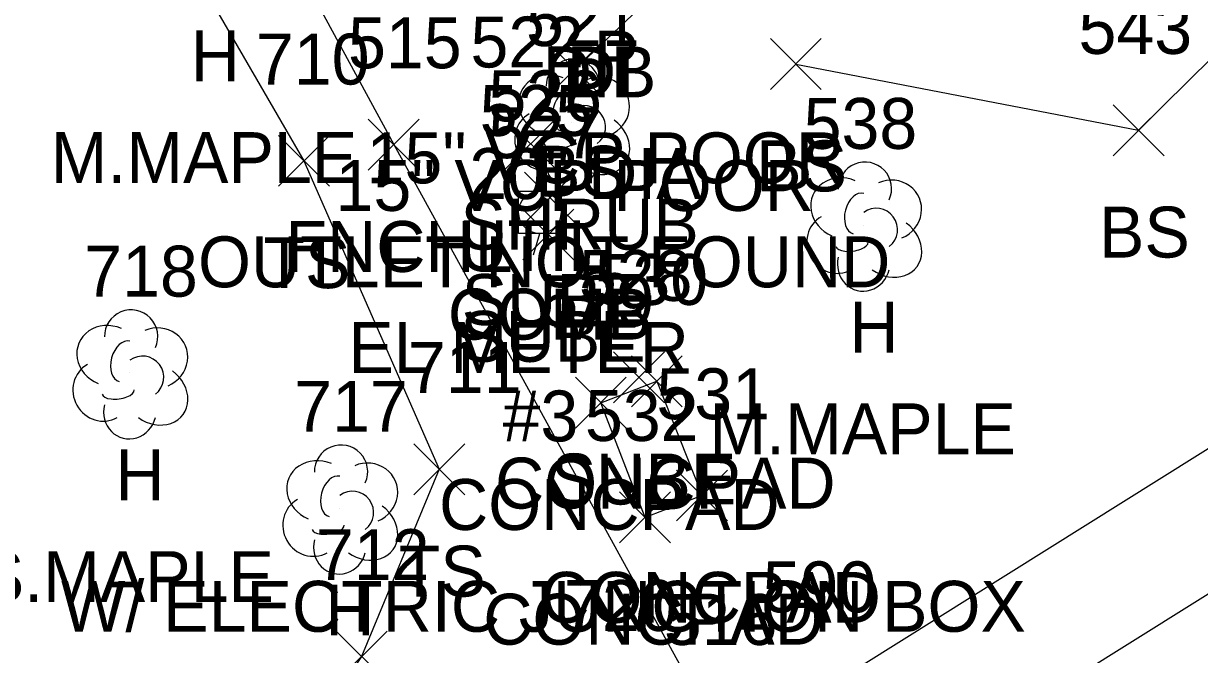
# Model space of a CAD drawing. Extents: x 1462668 to 1465147, y 550359 to 557351.
# Drawn here: x 1464779.74 to 1464825.93, y 552479.73 to 552504.51 of the extents above; entities that cross this region are included whole.
import ezdxf

# ---------------------------------------------------------------- set-up
doc = ezdxf.new("R2010")
doc.units = 0
for name, color, linetype in [('D_A', 7, 'Continuous'), ('D_C', 7, 'Continuous'), ('L_A', 7, 'Continuous'), ('L_C', 7, 'Continuous'), ('L_I', 7, 'Continuous'), ('L_TIC', 7, 'Continuous'), ('LELB', 7, 'Continuous'), ('LFNC', 7, 'Continuous'), ('LS', 7, 'Continuous'), ('LSH', 7, 'Continuous'), ('LTD', 7, 'Continuous'), ('R_I', 7, 'Continuous'), ('RSW', 7, 'Continuous'), ('U_A', 7, 'Continuous'), ('U_C', 7, 'Continuous'), ('U_I', 7, 'Continuous'), ('U_TIC', 7, 'Continuous'), ('UDEFAULT', 7, 'Continuous'), ('UP', 7, 'Continuous')]:
    doc.layers.add(name, color=color, linetype=linetype)

msp = doc.modelspace()

# ---------------------------------------------------------------- linework, layer by layer
at = {"layer": 'L_TIC'}
for points in [[(1464800.392, 552501.712), (1464802.392, 552503.712)], [(1464802.392, 552501.712), (1464800.392, 552503.712)], [(1464809.075, 552501.92), (1464811.075, 552503.92)], [(1464811.075, 552501.92), (1464809.075, 552503.92)], [(1464822.538, 552499.32), (1464824.538, 552501.32)], [(1464824.538, 552499.32), (1464822.538, 552501.32)], [(1464793.283, 552498.755), (1464795.283, 552500.755)], [(1464795.283, 552498.755), (1464793.283, 552500.755)], [(1464789.754, 552498.118), (1464791.754, 552500.118)], [(1464791.754, 552498.118), (1464789.754, 552500.118)], [(1464803.616, 552489.46), (1464805.616, 552491.46)], [(1464805.616, 552489.46), (1464803.616, 552491.46)], [(1464801.416, 552488.619), (1464803.416, 552490.619)], [(1464803.416, 552488.619), (1464801.416, 552490.619)], [(1464795.071, 552486.003), (1464797.071, 552488.003)], [(1464797.071, 552486.003), (1464795.071, 552488.003)], [(1464805.393, 552484.971), (1464807.393, 552486.971)], [(1464807.393, 552484.971), (1464805.393, 552486.971)], [(1464803.155, 552484.114), (1464805.155, 552486.114)], [(1464805.155, 552484.114), (1464803.155, 552486.114)], [(1464792.021, 552478.649), (1464794.021, 552480.649)], [(1464794.021, 552478.649), (1464792.021, 552480.649)]]:
    msp.add_lwpolyline(points, dxfattribs=at)
at = {"layer": 'LELB'}
for points in [[(1464810.075, 552502.92), (1464823.538, 552500.32), (1464840.949, 552517.528), (1464858.093, 552536.543), (1464872.967, 552537.834), (1464893.717, 552548.289), (1464880.456, 552556.962)], [(1464801.392, 552502.712), (1464812.723, 552513.459), (1464830.931, 552530.033)], [(1464783.661, 552511.372), (1464790.754, 552499.118), (1464796.071, 552487.003), (1464793.021, 552479.649), (1464787.448, 552471.22)]]:
    msp.add_lwpolyline(points, dxfattribs=at)
at = {"layer": 'LFNC'}
msp.add_lwpolyline([(1464775.324, 552529.154), (1464777.016, 552530.095), (1464787.863, 552511.628), (1464794.283, 552499.755), (1464806.74, 552477.101), (1464791.818, 552465.65), (1464787.35, 552464.648)], dxfattribs=at)
at = {"layer": 'LS'}
for points in [[(1464802.416, 552489.619), (1464804.616, 552490.46), (1464806.393, 552485.971), (1464804.155, 552485.114)], [(1464804.155, 552485.114), (1464802.416, 552489.619)]]:
    msp.add_lwpolyline(points, dxfattribs=at)
at = {"layer": 'LSH'}
msp.add_line((1464801.273, 552500.63), (1464801.273, 552500.63), dxfattribs=at)
msp.add_line((1464801.273, 552500.63), (1464801.273, 552500.63), dxfattribs=at)
msp.add_arc((1464801.319, 552502.064), 1.047, 335.5272, 180.9563, dxfattribs=at)
for centre, major_axis, ratio, start_param, end_param in [((1464800.481, 552501.297), (1.21, -0.512), 0.895232, 1.570796, 4.712389), ((1464802.314, 552501.214), (-1.141, -0.483), 0.949671, 1.570796, 4.712389), ((1464801.064, 552501.089), (-0.208, -0.792), 0.645439, 3.141593, 6.283185), ((1464801.773, 552500.464), (-0.5, 0.667), 0.989748, 3.141593, 6.283185), ((1464800.19, 552499.922), (0.584, -1.042), 0.959034, 3.141593, 6.283185), ((1464802.273, 552499.797), (-1.09, 0.792), 0.841452, 1.570796, 4.712389), ((1464800.815, 552499.88), (-0.625, -0.083), 0.423636, 0, 3.141593), ((1464801.273, 552499.13), (0.265, 1.061), 0.942809, 1.570796, 4.712389)]:
    msp.add_ellipse(centre, major_axis=major_axis, ratio=ratio, start_param=start_param, end_param=end_param, dxfattribs=at)
at = {"layer": 'LTD'}
for p, q in [((1464812.743, 552496.59), (1464812.743, 552496.59)), ((1464812.743, 552496.59), (1464812.743, 552496.59)), ((1464783.922, 552490.785), (1464783.922, 552490.785)), ((1464783.922, 552490.785), (1464783.922, 552490.785)), ((1464792.166, 552485.475), (1464792.166, 552485.475)), ((1464792.166, 552485.475), (1464792.166, 552485.475))]:
    msp.add_line(p, q, dxfattribs=at)
for centre in [(1464812.789, 552498.024), (1464783.969, 552492.219), (1464792.213, 552486.909)]:
    msp.add_arc(centre, 1.047, 335.5272, 180.9563, dxfattribs=at)
for centre, major_axis, ratio, start_param, end_param in [((1464811.951, 552497.257), (1.21, -0.512), 0.895232, 1.570796, 4.712389), ((1464813.784, 552497.174), (-1.141, -0.483), 0.949671, 1.570796, 4.712389), ((1464812.534, 552497.049), (-0.208, -0.792), 0.645439, 3.141593, 6.283185), ((1464813.243, 552496.424), (-0.5, 0.667), 0.989748, 3.141593, 6.283185), ((1464811.659, 552495.882), (0.584, -1.042), 0.959034, 3.141593, 6.283185), ((1464813.743, 552495.757), (-1.09, 0.792), 0.841452, 1.570796, 4.712389), ((1464812.284, 552495.84), (-0.625, -0.083), 0.423636, 0, 3.141593), ((1464812.743, 552495.09), (0.265, 1.061), 0.942809, 1.570796, 4.712389), ((1464783.131, 552491.451), (1.21, -0.512), 0.895232, 1.570796, 4.712389), ((1464784.964, 552491.368), (-1.141, -0.483), 0.949671, 1.570796, 4.712389), ((1464783.714, 552491.243), (-0.208, -0.792), 0.645439, 3.141593, 6.283185), ((1464784.422, 552490.618), (-0.5, 0.667), 0.989748, 3.141593, 6.283185), ((1464782.839, 552490.076), (0.584, -1.042), 0.959034, 3.141593, 6.283185), ((1464784.922, 552489.951), (-1.09, 0.792), 0.841452, 1.570796, 4.712389), ((1464783.464, 552490.035), (-0.625, -0.083), 0.423636, 0, 3.141593), ((1464783.923, 552489.285), (0.265, 1.061), 0.942809, 1.570796, 4.712389), ((1464791.375, 552486.142), (1.21, -0.512), 0.895232, 1.570796, 4.712389), ((1464793.208, 552486.059), (-1.141, -0.483), 0.949671, 1.570796, 4.712389), ((1464791.958, 552485.934), (-0.208, -0.792), 0.645439, 3.141593, 6.283185), ((1464792.666, 552485.309), (-0.5, 0.667), 0.989748, 3.141593, 6.283185), ((1464791.083, 552484.767), (0.584, -1.042), 0.959034, 3.141593, 6.283185), ((1464793.167, 552484.642), (-1.09, 0.792), 0.841452, 1.570796, 4.712389), ((1464791.708, 552484.725), (-0.625, -0.083), 0.423636, 0, 3.141593), ((1464792.167, 552483.975), (0.265, 1.061), 0.942809, 1.570796, 4.712389)]:
    msp.add_ellipse(centre, major_axis=major_axis, ratio=ratio, start_param=start_param, end_param=end_param, dxfattribs=at)
at = {"layer": 'RSW'}
for points in [[(1464915.201, 552543.476), (1464884.635, 552524.317), (1464849.312, 552502.23), (1464811.217, 552478.381), (1464802.402, 552472.947), (1464795.812, 552468.295), (1464792.637, 552465.36), (1464790.261, 552462.306), (1464792.645, 552456.479), (1464805.544, 552455.548), (1464830.453, 552453.838), (1464871.786, 552450.71), (1464920.525, 552447.504), (1464964.703, 552444.249), (1464969.112, 552445.273)], [(1464917.507, 552538.983), (1464887.388, 552520.242), (1464852.049, 552498.233), (1464813.823, 552474.305), (1464805.413, 552469.026), (1464798.984, 552464.868), (1464795.363, 552461.268), (1464805.707, 552460.324), (1464871.72, 552455.492), (1464920.401, 552452.145), (1464965.289, 552448.833), (1464968.154, 552449.785)]]:
    msp.add_lwpolyline(points, dxfattribs=at)
at = {"layer": 'U_TIC'}
for points in [[(1464799.416, 552496.672), (1464801.416, 552498.672)], [(1464801.416, 552496.672), (1464799.416, 552498.672)], [(1464799.357, 552495.224), (1464801.357, 552497.224)], [(1464801.357, 552495.224), (1464799.357, 552497.224)], [(1464802.916, 552489.619), (1464804.916, 552491.619)], [(1464804.916, 552489.619), (1464802.916, 552491.619)]]:
    msp.add_lwpolyline(points, dxfattribs=at)
at = {"layer": 'UDEFAULT'}
for points in [[(1464798.659, 552498.787), (1464800.659, 552500.787)], [(1464800.659, 552498.787), (1464798.659, 552500.787)]]:
    msp.add_lwpolyline(points, dxfattribs=at)
at = {"layer": 'UP'}
for p, q in [((1464800.271, 552498.765), (1464800.021, 552497.932)), ((1464799.188, 552496.265), (1464799.188, 552497.932)), ((1464799.188, 552497.932), (1464800.854, 552497.932)), ((1464800.854, 552497.932), (1464800.854, 552496.265)), ((1464800.021, 552497.098), (1464800.021, 552497.098)), ((1464800.854, 552496.265), (1464799.188, 552496.265)), ((1464799.771, 552495.432), (1464800.021, 552496.265))]:
    msp.add_line(p, q, dxfattribs=at)
msp.add_circle((1464800.021, 552497.098), 0.833, dxfattribs=at)

# ---------------------------------------------------------------- texts
at = {"layer": 'D_A'}
for s, p in [('P', (1464802.132, 552502.235)), ('DIB', (1464800.136, 552501.613)), ('DI', (1464801.083, 552501.62)), ('P', (1464800.911, 552501.152))]:
    msp.add_text(s, height=2, dxfattribs=at).set_placement(p)
at = {"layer": 'D_C'}
for s, p in [('15" VCP POOR', (1464793.218, 552498.235)), ('20" DIA', (1464797.248, 552497.62)), ('15" VCP POOR', (1464791.998, 552497.152)), ('OUTLET NOT FOUND', (1464786.596, 552494.152))]:
    msp.add_text(s, height=2, dxfattribs=at).set_placement(p)
at = {"layer": 'L_A'}
for s, p in [('H', (1464786.308, 552502.246)), ('BS', (1464808.516, 552497.92)), ('BS', (1464799.833, 552497.712)), ('SHRUB', (1464796.903, 552495.63)), ('BS', (1464821.979, 552495.32)), ('FNCHL', (1464790.031, 552494.755)), ('TS', (1464789.163, 552494.118)), ('H', (1464812.176, 552491.59)), ('H', (1464783.355, 552485.785)), ('CONCPAD', (1464798.261, 552485.46)), ('CONCPAD', (1464796.062, 552484.619)), ('TS', (1464794.48, 552482.003)), ('CONCPAD', (1464800.039, 552480.971)), ('H', (1464791.6, 552480.475)), ('CONCPAD', (1464797.8, 552480.114))]:
    msp.add_text(s, height=2, dxfattribs=at).set_placement(p)
at = {"layer": 'L_C'}
for s, p in [('M.MAPLE', (1464780.811, 552498.246)), ('M.MAPLE', (1464806.68, 552487.59)), ('S.MAPLE', (1464777.985, 552481.785)), ('W/ ELECTRIC JUNCTION BOX', (1464781.219, 552480.619))]:
    msp.add_text(s, height=2, dxfattribs=at).set_placement(p)
at = {"layer": 'L_I'}
for s, p in [('521', (1464799.477, 552503.63)), ('543', (1464821.176, 552503.32)), ('515', (1464792.488, 552502.755)), ('710', (1464788.872, 552502.118)), ('538', (1464810.38, 552499.59)), ('718', (1464782.127, 552493.785)), ('530', (1464802.167, 552493.46)), ('529', (1464800.046, 552492.619)), ('711', (1464794.842, 552490.003)), ('531', (1464804.598, 552488.971)), ('717', (1464790.371, 552488.475)), ('532', (1464801.792, 552488.114)), ('712', (1464791.226, 552482.649)), ('720', (1464800.968, 552480.653)), ('516', (1464804.889, 552480.101))]:
    msp.add_text(s, height=2, dxfattribs=at).set_placement(p)
at = {"layer": 'R_I'}
msp.add_text('590', height=2, dxfattribs=at).set_placement((1464808.768, 552481.381))
at = {"layer": 'U_A'}
for s, p in [('UTIL', (1464796.824, 552494.787)), ('SUBE', (1464796.952, 552492.672)), ('COMB', (1464796.407, 552492.098)), ('SUBE', (1464796.893, 552491.224)), ('SUBE', (1464800.451, 552485.619))]:
    msp.add_text(s, height=2, dxfattribs=at).set_placement(p)
at = {"layer": 'U_C'}
for s, p in [('EL METER', (1464792.501, 552490.787)), ('#3', (1464798.556, 552488.098))]:
    msp.add_text(s, height=2, dxfattribs=at).set_placement(p)
at = {"layer": 'U_I'}
for s, p in [('522', (1464797.296, 552502.787)), ('526', (1464797.999, 552500.672)), ('525', (1464797.659, 552500.098)), ('527', (1464797.995, 552499.224)), ('528', (1464801.554, 552493.619))]:
    msp.add_text(s, height=2, dxfattribs=at).set_placement(p)

doc.saveas('drawing.dxf')
